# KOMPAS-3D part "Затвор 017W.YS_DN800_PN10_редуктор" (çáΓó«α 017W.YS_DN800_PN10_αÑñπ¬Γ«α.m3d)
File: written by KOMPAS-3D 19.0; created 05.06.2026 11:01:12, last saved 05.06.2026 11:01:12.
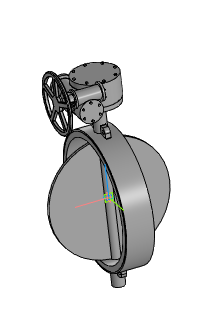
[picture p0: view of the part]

Document properties: Автор: Энергия; Полное имя файла: ..\..\..\3d для проектировщиков\x.x Тип 017W.Y(S) Затвор дисковый поворотный межфланцевый\Затвор 017W.Y(S)_DN50-DN1200_редуктор\Затвор 017W.YS_DN800_PN10_редуктор.a3d

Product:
- Part/product: Затвор 017W.YS_DN800_PN10_редуктор
    Масса: 469.065

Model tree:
1. Операция без истории:1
